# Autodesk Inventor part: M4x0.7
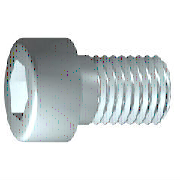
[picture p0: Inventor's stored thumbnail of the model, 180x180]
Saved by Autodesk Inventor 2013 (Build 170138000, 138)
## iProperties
Created: 2009-02
Part Number: M4x0.7
Material: 강, 연강
Description: 6각머리 태핑 나사
Document SubType Name: Modeling
Standard: KS B 1003
Standards Organization: KS
Language: ko-KR
Size Designation: M 4 x 12
Categories: <MemberInstance><Categories><Category DisplayName="조임쇠" InternalName="e4da775c-781d-43d5-af7c-5136215cf5a6" Mnemonic="FSTN"><Category DisplayName="볼트" InternalN
Density: 1 g/cm^3
Checked By: KYOUNG IL JANG
Vendor: CBT Solutions
Designer: KYOUNG IL JANG
Manager: KYOUNG IL JANG
Company: 한국ATC센터
IsCustomPart: 0
Author: KYOUNG IL JANG
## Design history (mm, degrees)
sketch "스케치1"
  geometry: L1 (-1, 0)-(12, 0); L2 (12, 0)-(12, 2); L3 (12, 2)-(1.75, 2); L4 (1.75, 2)-(1.32, 2); L5 (1.32, 2)-(0, 2); L6 (0, 2)-(0, 3.5); L7 (0, 3.5)-(-4, 3.5); L8 (-4, 3.5)-(-4, 1.732); L9 (-4, 1.732)-(-2, 1.732); L10 (-2, 1.732)-(-1, 0); L11 (-7.2, 0)-(15.2, 0) reference; L12 (0, -0.7)-(0, 4.2) reference; L13 (1.75, 2)-(0, 2)
  constraints: 22 end point, 6 parallel, 2 collinear, 2 perpendicular, 1 horizontal, 1 point on line
  dimensions: "d1" = 10.25 distance from line of L3.end L2 (= GEL); "d2" = 0.42952 distance of L4.end L3.end (computed from GAL); "d3" = 4 distance between parallel lines of L8 L6 (= KOH); "d4" = 2 distance of L8.end L9.end (= INTI); "d5" = 60 deg angle of L10 L1; "d6" = 4 diameter of L3 L1 (= GD); "d7" = 4 diameter of L5 L1 (= BDM); "d8" = 3.4641 diameter of L9 L1 (= 1.1547 x SW); "d9" = 7 diameter of L7 L1 (= KOD); "d26" = 12 distance between parallel lines of L12 L2 (= NLG)
revolve "본체" sketch "스케치1" stored, may be unused: angle "d10" = 90 deg
sketch "스케치2"
  geometry: L1 (0, -4.9)-(0, 4.9) reference; L2 (-4.9, 0)-(4.9, 0) reference; L3 (1.732, 0)-(0.866, -1.5); L4 (0.866, -1.5)-(-0.866, -1.5); L5 (-0.866, -1.5)-(-1.732, 0); L6 (-1.732, 0)-(-0.866, 1.5); L7 (-0.866, 1.5)-(0.866, 1.5); L8 (0.866, 1.5)-(1.732, 0); 2 further points
  constraints: 12 end point, 1 coincident, 1 horizontal alignment, 1 point on line, 12 other
extrude "슬롯" join sketch "스케치2" stored distance "d11" = 10; taper "d12" = 0 deg
workplane "Work Plane1"
fillet "Fillet2" dims "d30" = 0.1 (= R)
body "Solid1"
fillet "모깎기1" dims "d17" = 0.4 (= RR)
feature "스레드" dims "d13" = 10.25 (= GEL), "d14" = 0
chamfer "모따기1" distance "d15" = 0.42941 (= -0.5 x SPD + 0.5 x GD); stored, may be unused: second distance "d16" = 0.42941 (= GUL), angle "d27" = 45 deg
other parameters: "GD" = 4 (= NND) [user parameter; used in 2 equation terms], "NLG" = 12 [user parameter; used in 1 equation term], "GEL" = 10.25 [user parameter; used in 2 equation terms], "KOD" = 7 [user parameter; used in 1 equation term], "KOH" = 4 [user parameter; used in 1 equation term], "INTI" = 2 [user parameter; used in 1 equation term], "GAL" = 0.42941 (= 0.61345 x PTC) [user parameter; used in 1 equation term], "GUL" = 0.42941 (= 0.61345 x PTC) [user parameter; used in 1 equation term], "BDM" = 4 (= NND) [user parameter; used in 1 equation term], "SW" = 3 [user parameter; used in 2 equation terms], "RR" = 0.4 [user parameter; used in 1 equation term], "SPD" = 3.14117 (= NND - 1.2269 x PTC) [user parameter; used in 1 equation term], "d19" = 0, "d28" = 0, "d29" = 0, "R" = 0.1 [user parameter; used in 1 equation term], "PHH" = 0.2 [user parameter], "GD1" = 3.14117 (= THREADDIA - 1.2269 x PTC) [user parameter], "THREADDIA" = 4 [user parameter; used in 1 equation term], "FAWI" = 45 deg [user parameter], "TPU" = 14.28571 (computed from PTC) [user parameter], "PTC" = 0.7 [user parameter; used in 5 equation terms], "NND" = 4 [user parameter; used in 3 equation terms], "TOA" = 30 deg [user parameter], "E0" = 3.465 (= 1.155 x SW) [user parameter]
